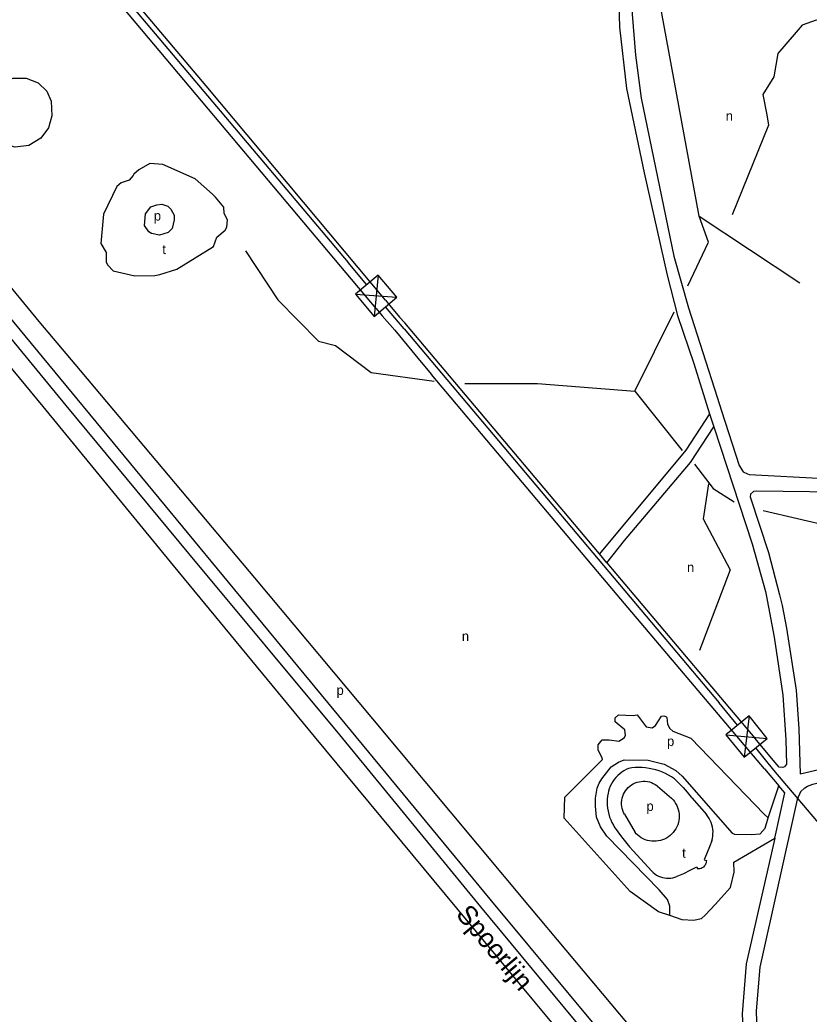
# Model space of a CAD drawing. Extents: x 158142 to 159655, y 385262 to 387204.
# Drawn here: x 158478 to 158802.8, y 385994 to 386403.5 of the extents above; entities that cross this region are included whole.
import ezdxf

# ---------------------------------------------------------------- set-up
doc = ezdxf.new("R2010")
doc.units = 0
for name, color, linetype in [('BLT_Basislijn', 7, 'Continuous'), ('BLT_Centroide', 7, 'Continuous'), ('BLT_Hoogspanningsmast_en_leidingen', 7, 'Continuous'), ('BLT_Spoorlijn', 7, 'Continuous'), ('BLT_Waternaam_spoorwegen', 7, 'Continuous')]:
    doc.layers.add(name, color=color, linetype=linetype)

msp = doc.modelspace()

# ---------------------------------------------------------------- linework, layer by layer
at = {"layer": 'BLT_Basislijn'}
for p, q in [((158423.26, 386354.85), (158485.76, 386279.3)), ((158624.65, 386284.64), (158627.07, 386281.62)), ((158628.46, 386287.97), (158630.21, 386285.88)), ((158630.21, 386285.88), (158634.29, 386280.97)), ((158632.35, 386275.68), (158627.07, 386281.62)), ((158636.38, 386278.74), (158634.29, 386280.97)), ((158731.13, 386250.6), (158747.25, 386283.26)), ((158485.76, 386279.3), (158502.75, 386259.09)), ((158716.61, 386183.55), (158636.38, 386278.74)), ((158632.35, 386275.68), (158642.41, 386263.37)), ((158642.41, 386263.37), (158647.33, 386257.48)), ((158502.75, 386259.09), (158516.46, 386242.78)), ((158764.97, 386248.15), (158766.75, 386242.48)), ((158516.46, 386242.78), (158574.57, 386173.66)), ((158761.86, 386241.17), (158763.62, 386235.89)), ((158784, 386201.42), (158827.48, 386191.22)), ((158719.63, 386179.9), (158716.61, 386183.55)), ((158574.57, 386173.66), (158623.12, 386115.52)), ((158623.12, 386115.52), (158687.8, 386038.09)), ((158784.53, 386094.97), (158790.33, 386087.93)), ((158740.49, 386087.87), (158746.23, 386082.85)), ((158786.04, 386074.84), (158790.33, 386087.93)), ((158754.53, 386083.11), (158760.57, 386076.14)), ((158726.79, 386076.26), (158731.2, 386068.72)), ((158730.39, 386061.17), (158738.06, 386052.85)), ((158759.58, 386057.49), (158760.55, 386057.26)), ((158756.62, 386054.58), (158756.9, 386053.74)), ((158687.8, 386038.09), (158748.89, 385965.22))]:
    msp.add_line(p, q, dxfattribs=at)
for points in [[(158757.54, 386322.67), (158737.93, 386429.5), (158749.55, 386456.64), (158812.62, 386491.7), (158821.39, 386499.37), (158817.14, 386522.92), (158812.61, 386535.9)], [(158726.28, 386506.62), (158727, 386504.84), (158732.89, 386493.7), (158741.5, 386474.16), (158738.85, 386465.87), (158733.82, 386454.83), (158729.3, 386442.97), (158726.5, 386430.65), (158725.78, 386425.75), (158724.61, 386415.86), (158724.5, 386409.95), (158724.83, 386400.43), (158727.71, 386375.28), (158734.92, 386340.45), (158744.35, 386298.39), (158748.73, 386281.78), (158755.35, 386261.93), (158761.86, 386241.17)], [(158624.65, 386284.64), (158490.91, 386443.67), (158478.8, 386457.87)], [(158628.46, 386287.97), (158554.58, 386376.36), (158484.51, 386459.46)], [(158734.85, 386441.17), (158732.67, 386434.38), (158731.21, 386428.49), (158730.09, 386419.09), (158730.02, 386405.84), (158731.42, 386388.95), (158733.76, 386371.24), (158747.12, 386306.2), (158753.2, 386284.87), (158764.97, 386248.15)], [(158820.92, 386402.37), (158805.76, 386403.38), (158800.05, 386401.35), (158789.96, 386389.69), (158788.28, 386379.99), (158783.8, 386372.81), (158785.38, 386364.31), (158786.18, 386360.05), (158771.15, 386323.25)], [(158375.75, 386399.25), (158436.99, 386325.27), (158671.45, 386041.29)], [(158557.25, 386331.64), (158550.07, 386338.01), (158536.78, 386343.89), (158531.51, 386344.29), (158526.92, 386341.71), (158524.84, 386339.98), (158524.64, 386339.37), (158522.88, 386337.53), (158519.6, 386336.38), (158517.84, 386334.81), (158512.43, 386323.47), (158511.31, 386311.31), (158513.5, 386307.63), (158513.5, 386303.65), (158514.13, 386302.45), (158516.36, 386300.09), (158525.33, 386298.01), (158533.47, 386298.25), (158535.54, 386298.56), (158542.54, 386300.86), (158557.68, 386310.14), (158559.04, 386313.93), (158562.48, 386316.91), (158563.11, 386318.13), (158563.43, 386321.15), (158562.11, 386323.78), (158561.84, 386326.4), (158558.5, 386330.53), (158557.25, 386331.64)], [(158541.49, 386321.06), (158540.69, 386317.55), (158539.01, 386315.84), (158535.44, 386314.87), (158532.1, 386315.52), (158531.09, 386316.22), (158529.24, 386318.76), (158529.72, 386323.53), (158531.86, 386326.52), (158534.33, 386327.34), (158536.4, 386327.51), (158538.88, 386326.71), (158540.06, 386325.52), (158541.49, 386323.06), (158541.49, 386321.06)], [(158752.86, 386293.97), (158761.38, 386311.95), (158757.54, 386322.67), (158799.04, 386295.16)], [(158570.76, 386308.41), (158584.18, 386288.13), (158600.9, 386271.21), (158607.88, 386269.3), (158622.55, 386258.31), (158648.49, 386254.62)], [(158784.53, 386094.97), (158723.84, 386166.67), (158647.33, 386257.48)], [(158661.16, 386253.73), (158690.99, 386253.73), (158731.13, 386250.6), (158750.62, 386226.18)], [(158761.86, 386241.17), (158752.05, 386226.21), (158716.61, 386183.55)], [(158766.75, 386242.48), (158773.99, 386219.91), (158775.65, 386217.36), (158777.55, 386216.46), (158778.19, 386216.19), (158809.3, 386214.52), (158817.41, 386214.84), (158822.79, 386216.21)], [(158719.63, 386179.9), (158726.91, 386189.01), (158753.95, 386221.12), (158763.62, 386235.89)], [(158763.62, 386235.89), (158779.35, 386187.68), (158784.96, 386168), (158785.21, 386166.67), (158788.49, 386149.19), (158792.09, 386125.27), (158793.32, 386106.97), (158793.55, 386096.91), (158792.69, 386095.8), (158792.05, 386095.6), (158790.51, 386095.67), (158788.86, 386097.61), (158780.49, 386107.56)], [(158755.73, 386220.5), (158763.34, 386210.48), (158772.05, 386204.99)], [(158761.49, 386212.32), (158759.22, 386197.92), (158770.35, 386176.98), (158757.79, 386143.67)], [(158821.41, 386209.88), (158819.62, 386209.45), (158813.97, 386208.96), (158781.24, 386209.43), (158779.93, 386209.28), (158778.74, 386208.13), (158778.55, 386207.06), (158786.18, 386184.09), (158790.63, 386166.67), (158791.76, 386162.26), (158793.56, 386152.97), (158797.45, 386127.33), (158798.64, 386111.47), (158799.12, 386093), (158890.75, 386114.16)], [(158719.63, 386179.9), (158730.74, 386166.67), (158780.49, 386107.56)], [(158801.15, 386087.19), (158802.13, 386087.88), (158804.38, 386088.68), (158819.59, 386092.57), (158864.39, 386103.2), (158969.86, 386127.19), (158991.64, 386131.66), (158991.49, 386130.98), (158892.61, 385993.92), (158884.81, 385983.47)], [(158745.5, 386034.53), (158740.82, 386036.07), (158729.21, 386044.49), (158702.03, 386074.61), (158702.24, 386083.36), (158717.73, 386098.84), (158717.64, 386099.58), (158716.02, 386102.69), (158715.95, 386104.86), (158717.69, 386106.89), (158720.49, 386106.91), (158724.53, 386106.38), (158726.76, 386107.79), (158727.24, 386108.74), (158726.98, 386111.05), (158723.01, 386114.37), (158722.94, 386116), (158724.31, 386117.3), (158730.42, 386116.98), (158732.07, 386117.17), (158735.73, 386112.24), (158738.21, 386111.89), (158739.58, 386112.82), (158742.12, 386116.63), (158743.08, 386116.82), (158743.86, 386116.51), (158744.28, 386116.14), (158744.61, 386113.44), (158745.47, 386111.58), (158746.71, 386110.48), (158754.18, 386107.57), (158784.33, 386076.31), (158786.04, 386074.84)], [(158745.5, 386034.53), (158745.52, 386038.39), (158744.51, 386041.11), (158741.09, 386045.12), (158719.62, 386067.24), (158716.93, 386071.14), (158715.37, 386075.12), (158714.89, 386079.61), (158714.95, 386082.89), (158715.63, 386086.99), (158716.38, 386089.03), (158717.54, 386090.93), (158721.35, 386095.8), (158724.39, 386097.73), (158726.7, 386098.76), (158736.61, 386098.62), (158743.14, 386096.85), (158747.99, 386094.26), (158750.61, 386091.98), (158771.14, 386068.53), (158772.1, 386068.13), (158778.95, 386067.97), (158782.74, 386068.19), (158784.77, 386070.53), (158786.04, 386074.84)], [(158728.53, 386095.18), (158727.56, 386094.72), (158726.62, 386094.19), (158725.72, 386093.59), (158724.88, 386092.93), (158724.08, 386092.21), (158723.34, 386091.43), (158722.65, 386090.59), (158722.04, 386089.71), (158721.49, 386088.79), (158721.01, 386087.82), (158720.6, 386086.82), (158720.27, 386085.8), (158720.06, 386084.97)], [(158747.43, 386090.89), (158746.24, 386091.68), (158745.01, 386092.4), (158743.74, 386093.05), (158742.43, 386093.63), (158741.1, 386094.14), (158739.73, 386094.56), (158738.35, 386094.92), (158736.95, 386095.19), (158735.53, 386095.38), (158734.11, 386095.5), (158732.68, 386095.53), (158731.25, 386095.49), (158729.83, 386095.36), (158728.53, 386095.18)], [(158726.79, 386076.26), (158726.41, 386077.03), (158726.1, 386077.82), (158725.87, 386078.65), (158725.71, 386079.49), (158725.64, 386080.34), (158725.64, 386081.19), (158725.72, 386082.05), (158725.89, 386082.89), (158726.13, 386083.71), (158726.45, 386084.5), (158726.84, 386085.26), (158727.29, 386085.98), (158727.82, 386086.66), (158728.4, 386087.28), (158729.04, 386087.85), (158729.73, 386088.35), (158730.47, 386088.79), (158731.24, 386089.16), (158732.05, 386089.45), (158732.87, 386089.67), (158733.72, 386089.81), (158734.57, 386089.87), (158735.42, 386089.85), (158736.27, 386089.74), (158737.11, 386089.57), (158737.93, 386089.31), (158738.71, 386088.98), (158739.47, 386088.57), (158740.18, 386088.1), (158740.49, 386087.87)], [(158747.43, 386090.89), (158749.24, 386089.1), (158750.99, 386087.24), (158752.68, 386085.34), (158754.31, 386083.38), (158754.53, 386083.11)], [(158720.06, 386084.97), (158719.86, 386083.74), (158719.75, 386082.5), (158719.71, 386081.25), (158719.76, 386080.01), (158719.89, 386078.77), (158720.09, 386077.54), (158720.37, 386076.33), (158720.73, 386075.14), (158721.17, 386073.97), (158721.68, 386072.84), (158722.26, 386071.74), (158722.61, 386071.15)], [(158788.76, 386066.43), (158792.82, 386085.05), (158790.33, 386087.93)], [(158801.15, 386087.19), (158799.25, 386085.57), (158797.86, 386082.34)], [(158746.23, 386082.85), (158746.85, 386082.18), (158747.41, 386081.47), (158747.91, 386080.71), (158748.34, 386079.91), (158748.69, 386079.07), (158748.97, 386078.21), (158749.18, 386077.32), (158749.3, 386076.42), (158749.35, 386075.52), (158749.31, 386074.61), (158749.2, 386073.71), (158749.01, 386072.82), (158748.74, 386071.95), (158748.39, 386071.11), (158747.97, 386070.3), (158747.49, 386069.54), (158746.93, 386068.82), (158746.32, 386068.15), (158745.65, 386067.53), (158744.93, 386066.98), (158744.16, 386066.49), (158743.35, 386066.08), (158742.51, 386065.73), (158741.64, 386065.47), (158740.76, 386065.27), (158739.85, 386065.16), (158738.95, 386065.13), (158738.04, 386065.17), (158737.14, 386065.3), (158736.25, 386065.51), (158735.39, 386065.79), (158734.56, 386066.14), (158733.75, 386066.57), (158732.99, 386067.07), (158732.28, 386067.63), (158731.62, 386068.26), (158731.2, 386068.72)], [(158797.86, 386082.34), (158782.58, 386013.26), (158781.07, 385995.34), (158781.47, 385981.54), (158782.58, 385974.52), (158785.44, 385968.1), (158802.81, 385947.04)], [(158762.77, 386065.35), (158763.02, 386066.27), (158763.18, 386067.21), (158763.27, 386068.17), (158763.28, 386069.12), (158763.21, 386070.08), (158763.06, 386071.02), (158762.83, 386071.95), (158762.52, 386072.85), (158762.14, 386073.73), (158761.69, 386074.57), (158761.17, 386075.37), (158760.57, 386076.14)], [(158722.61, 386071.15), (158724.08, 386069.01), (158725.62, 386066.92), (158727.22, 386064.87), (158728.88, 386062.87), (158730.39, 386061.17)], [(158762.77, 386065.35), (158761.89, 386062.93), (158760.93, 386060.53), (158759.89, 386058.17), (158759.58, 386057.49)], [(158764.13, 386039.08), (158770.5, 386046.07), (158771.96, 386052.39), (158771.8, 386056.49), (158788.76, 386066.43)], [(158788.76, 386066.43), (158776.94, 386014.68), (158775.34, 385994.1), (158775.97, 385980.27)], [(158760.55, 386057.26), (158760.53, 386056.74), (158760.43, 386056.23), (158760.26, 386055.74), (158760.01, 386055.28), (158759.69, 386054.86), (158759.31, 386054.5), (158758.88, 386054.2), (158758.42, 386053.97), (158757.92, 386053.82), (158757.4, 386053.74), (158756.9, 386053.74)], [(158738.06, 386052.85), (158738.68, 386052.25), (158739.35, 386051.72), (158740.07, 386051.24), (158740.83, 386050.84), (158741.63, 386050.51), (158742.45, 386050.25), (158743.29, 386050.07), (158744.15, 386049.98), (158745.01, 386049.95), (158745.87, 386050.01), (158746.71, 386050.15), (158747.55, 386050.37), (158748.36, 386050.67), (158748.49, 386050.72)], [(158748.49, 386050.72), (158751.23, 386051.93), (158753.93, 386053.21), (158756.62, 386054.58)], [(158671.45, 386041.29), (158735.98, 385963.55), (158865.51, 385806.81)], [(158764.13, 386039.08), (158760.18, 386034.86), (158758.41, 386033.2), (158755.45, 386032.5), (158750.55, 386032.78), (158745.5, 386034.53)]]:
    msp.add_lwpolyline(points, dxfattribs=at)
msp.add_lwpolyline([(158463.9, 386367.83), (158466.34, 386373.48), (158470.6, 386377.64), (158475.18, 386379.44), (158480.52, 386379.44), (158485.47, 386377.5), (158489.04, 386374.06), (158490.86, 386369.95), (158491.12, 386363.97), (158489.69, 386359.01), (158486.63, 386354.7), (158481.7, 386351.75), (158475.94, 386351.02), (158470.07, 386352.64), (158465.84, 386356.11), (158463.67, 386362.21)], close=True, dxfattribs=at)
at = {"layer": 'BLT_Hoogspanningsmast_en_leidingen'}
for p, q in [((158482.67, 386458.3), (158613.07, 386303.54)), ((158620.77, 386294.42), (158613.07, 386303.54)), ((158625.47, 386298.39), (158623.77, 386281.33)), ((158616.07, 386290.45), (158633.18, 386289.28)), ((158636.18, 386276.19), (158628.48, 386285.3)), ((158636.18, 386276.19), (158765.8, 386122.2)), ((158773.32, 386112.93), (158765.8, 386122.2)), ((158778.11, 386116.81), (158776.07, 386099.79)), ((158768.54, 386109.05), (158785.63, 386107.55)), ((158788.37, 386094.4), (158780.85, 386103.67)), ((158914.81, 385944.55), (158788.37, 386094.4))]:
    msp.add_line(p, q, dxfattribs=at)
for points in [[(158623.77, 386281.33), (158633.18, 386289.28), (158625.47, 386298.39), (158616.07, 386290.45)], [(158776.07, 386099.79), (158785.63, 386107.55), (158778.11, 386116.81), (158768.54, 386109.05)]]:
    msp.add_lwpolyline(points, close=True, dxfattribs=at)
at = {"layer": 'BLT_Spoorlijn'}
for points in [[(158423.58, 386321.46), (158487.33, 386244.19)], [(158433.14, 386322.09), (158496.88, 386244.66)], [(158487.33, 386244.19), (158541.05, 386178.68)], [(158496.88, 386244.66), (158547.31, 386183.69)], [(158547.31, 386183.69), (158609.49, 386108.93)], [(158541.05, 386178.68), (158599.15, 386108.31)], [(158609.49, 386108.93), (158667.6, 386038.09)], [(158599.15, 386108.31), (158657.73, 386037.62)], [(158657.73, 386037.62), (158722.42, 385959.57)], [(158667.6, 386038.09), (158732.13, 385960.36)]]:
    msp.add_lwpolyline(points, dxfattribs=at)

# ---------------------------------------------------------------- texts
at = {"layer": 'BLT_Centroide'}
for s, p in [('n', (158768.51, 386361.92)), ('p', (158533.08, 386320.81)), ('t', (158536.59, 386307)), ('n', (158752.57, 386176)), ('n', (158659.9, 386147.64)), ('p', (158608.3, 386125.43)), ('p', (158744.36, 386104.38)), ('p', (158735.88, 386077.63)), ('t', (158750.56, 386058.37))]:
    msp.add_text(s, height=4, dxfattribs=at).set_placement(p)
at = {"layer": 'BLT_Waternaam_spoorwegen'}
msp.add_text('Spoorlijn', height=8, rotation=309.8574, dxfattribs=at).set_placement((158657.12, 386034.84))

doc.saveas('drawing.dxf')
